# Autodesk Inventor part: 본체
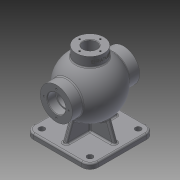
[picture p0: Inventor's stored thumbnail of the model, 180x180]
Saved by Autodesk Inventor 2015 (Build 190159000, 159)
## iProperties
Created: 2025-08
Part Number: 본체
Material: 일반
Document SubType Name: Modeling
Designer: user
Density: 1 g/cm^3
Appearance: 기본값
Author: user
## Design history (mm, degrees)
sketch "스케치2"
  geometry: L1 (-62.5, -62.5)-(62.5, -62.5); L2 (62.5, -62.5)-(62.5, 62.5); L3 (62.5, 62.5)-(-62.5, 62.5); L4 (-62.5, 62.5)-(-62.5, -62.5); L5 (-62.5, -62.5)-(62.5, 62.5); L6 (62.5, -62.5)-(-62.5, 62.5); 1 further point
  constraints: 12 end point, 2 midpoint, 2 parallel, 1 horizontal, 1 perpendicular
  dimensions: "d0" = 125 distance of L3.end L2.end; "d1" = 125 distance of L2.end L1.end
extrude "돌출1" new body sketch "스케치2" distance "d2" = 10; taper "d3" = 0 deg
sketch "스케치6"
  geometry: L1 (-62.5, 0)-(-62.5, 10) reference; L2 (-62.5, 10)-(62.5, 10) reference; L3 (62.5, 10)-(62.5, 0) reference; L4 (62.5, 0)-(-62.5, 0) reference; L5 (0, 139)-(0, 31); A1 r 54 centre (0, 85) between (0, 139) and (0, 31); 3 further points
  constraints: 2 end point, 2 midpoint, 2 point on circle, 2 vertical alignment, 1 centre point, 1 coincident, 1 vertical
  dimensions: "d11" = 108 diameter of A1; "d12" = 85 distance from line of A1.centre L4
revolve "회전3" sketch "스케치6" stored, may be unused: angle "d13" = 90 deg
node "작업 평면1"
sketch "스케치7"
  geometry: C1 r 27 at (0, 0); 1 further point
  constraints: 1 centre point, 1 coincident
  dimensions: "d15" = 54 diameter of C1
extrude "돌출2" join sketch "스케치7" stored distance "d16" = 10; taper "d17" = 0 deg
sketch "스케치9"
  geometry: L1 (62.5, -62.5)-(-62.5, -62.5) reference; L2 (-62.5, -62.5)-(-62.5, 62.5) reference; L3 (-62.5, 62.5)-(62.5, 62.5) reference; L4 (62.5, 62.5)-(62.5, -62.5) reference; L5 (-4, -50.5)-(4, -50.5); L6 (4, -50.5)-(4, 50.5); L7 (4, 50.5)-(-4, 50.5); L8 (-4, 50.5)-(-4, -50.5); L9 (-4, -50.5)-(4, 50.5); L10 (4, -50.5)-(-4, 50.5); L11 (-50.5, -4)-(50.5, -4); L12 (50.5, -4)-(50.5, 4); L13 (50.5, 4)-(-50.5, 4); L14 (-50.5, 4)-(-50.5, -4); L15 (-50.5, -4)-(50.5, 4); L16 (50.5, -4)-(-50.5, 4); 1 further point
  constraints: 24 end point, 4 midpoint, 4 parallel, 2 horizontal, 2 perpendicular
  dimensions: "d26" = 8 distance of L6.end L7.end; "d27" = 8 distance of L11.end L12.end; "d28" = 12 distance between parallel lines of L12 L4; "d29" = 12 distance between parallel lines of L7 L3
extrude "돌출4" join sketch "스케치9" distance "d30" = 90; taper "d31" = 0 deg
feature "면 기울기1" dims angle "d32" = 20 deg
node "작업 평면2"
sketch "스케치10"
  geometry: L1 (62.5, 0)-(-62.5, 0) reference; C1 r 31 at (0, 85); 2 further points
  constraints: 1 centre point, 1 midpoint, 1 vertical alignment
  dimensions: "d34" = 62 diameter of C1; "d35" = 85 distance from line of C1.centre L1
extrude "돌출5" join sketch "스케치10" distance "d36" = 130; taper "d37" = 0 deg
sketch "스케치11"
  geometry: L1 (-27, 131.765)-(-27, 150) reference; L2 (-27, 150)-(27, 150) reference; L3 (27, 150)-(27, 131.765) reference; L4 (37.385, 46.034)-(50.5, 10) reference; L5 (50.5, 10)-(62.5, 10) reference; L6 (62.5, 10)-(62.5, 0) reference; L7 (62.5, 0)-(-62.5, 0) reference; L8 (-62.5, 0)-(-62.5, 10) reference; L9 (-62.5, 10)-(-50.5, 10) reference; L10 (-50.5, 10)-(-37.385, 46.034) reference; L11 (0, 129)-(0, 41); A1 r 54 centre (0, 85) between (37.385, 46.034) and (27, 131.765) reference; A2 r 54 centre (0, 85) between (-27, 131.765) and (-37.385, 46.034) reference; A3 r 44 centre (0, 85) between (0, 129) and (0, 41); 3 further points
  constraints: 2 coincident, 2 end point, 2 midpoint, 2 point on circle, 1 centre point, 1 vertical, 1 vertical alignment
  dimensions: "d38" = 88 diameter of A3
revolve "회전4" sketch "스케치11" stored, may be unused: angle "d39" = 90 deg
sketch "스케치14"
  geometry: C1 r 27 at (0, 0) reference; C2 r 13 at (0, 0); 1 further point
  constraints: 1 centre point, 1 coincident
  dimensions: "d41" = 26 diameter of C2
extrude "돌출6" cut sketch "스케치14" distance "d42" = 40; taper "d43" = 0 deg
hole "구멍1" diameter "d46" = 30; stored, may be unused: countersink angle "d50" = 90 deg, drill point angle "d52" = 0 deg; dims "d44" = 10, "d45" = 10, "d47" = 12, "d48" = 35, "d49" = 16, "d51" = 30
sketch "스케치19"
  geometry: L1 (0, 0)-(0, 24); C1 r 17.5 at (0, 0) reference; 1 further point
  constraints: 2 end point, 1 vertical
  dimensions: "d54" = 24 distance of L1.start L1.end
hole "구멍2" sketch "스케치19" at (0, 24) diameter "d55" = 3.242; stored, may be unused: countersink angle "d59" = 90 deg, drill point angle "d61" = 118 deg; dims "d56" = 12, "d57" = 35, "d58" = 16, "d60" = 15
sketch "스케치20"
  geometry: L1 (0, 0)-(0, 20)
  constraints: 2 end point, 1 vertical
  dimensions: "d65" = 20 distance of L1.start L1.end
hole "구멍3" sketch "스케치20" at (0, 20) diameter "d66" = 3.242; stored, may be unused: countersink angle "d70" = 90 deg, drill point angle "d72" = 118 deg; dims "d67" = 9, "d68" = 35, "d69" = 16, "d71" = 11
node "작업 평면3"
sketch "스케치21"
  geometry: L1 (-27, 150)-(27, 150) reference; 2 further points
  constraints: 1 vertical alignment, 1 other
  dimensions: "d77" = 9 distance from line of point (0, 141) L1
feature "엠보싱1" sketch "스케치21" dims "d0" = 125, "d1" = 125, "d78" = 0.5, "d79" = 0
fillet "모깎기1" dims "d80" = 3
fillet "모깎기2" dims "d81" = 3
fillet "모깎기3" dims "d82" = 3
fillet "모깎기4" dims "d83" = 16
hole "구멍4" diameter "d86" = 11; stored, may be unused: countersink angle "d90" = 90 deg, drill point angle "d92" = 118 deg; dims "d84" = 10, "d85" = 10, "d87" = 9, "d88" = 35, "d89" = 16, "d91" = 11
hole "구멍5" diameter "d95" = 11; stored, may be unused: countersink angle "d99" = 90 deg, drill point angle "d101" = 118 deg; dims "d93" = 10, "d94" = 10, "d96" = 9, "d97" = 35, "d98" = 16, "d100" = 11
hole "구멍6" diameter "d104" = 11; stored, may be unused: countersink angle "d108" = 90 deg, drill point angle "d110" = 118 deg; dims "d102" = 10, "d103" = 10, "d105" = 9, "d106" = 35, "d107" = 16, "d109" = 11
hole "구멍7" diameter "d113" = 11; stored, may be unused: countersink angle "d117" = 90 deg, drill point angle "d119" = 118 deg; dims "d111" = 10, "d112" = 10, "d114" = 9, "d115" = 35, "d116" = 16, "d118" = 11
fillet "모깎기5" dims "d120" = 3
chamfer "모따기1" distance "d121" = 1; stored, may be unused: second distance "d122" = 2, angle "d123" = 45 deg
node "솔리드1"
mirror "대칭1"
pattern_circular "원형 패턴1" dims angle "d63" = 360 deg
mirror "대칭2"
pattern_circular "원형 패턴2" dims angle "d74" = 360 deg
node "절단 모서리 투영1"
node "절단 모서리 투영3"
node "절단 모서리 투영4"
node "절단 모서리 투영5"
other parameters: "d33" = -65, "d76" = 142.5
